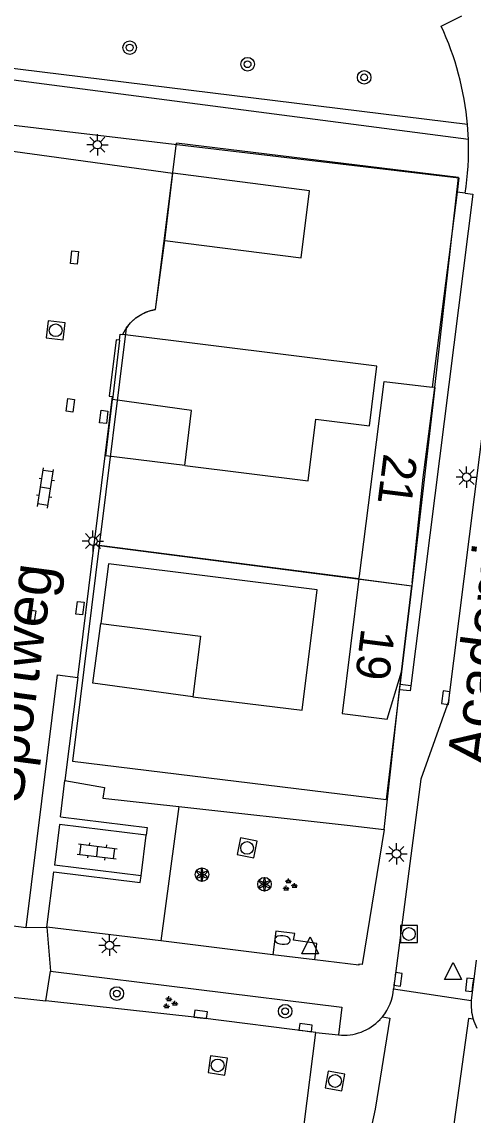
# Model space of a CAD drawing. Extents: x 131000 to 133014, y 396499 to 399001.
# Drawn here: x 132103.1 to 132129.7, y 397102.9 to 397167.2 of the extents above; entities that cross this region are included whole.
import ezdxf

# ---------------------------------------------------------------- set-up
doc = ezdxf.new("R2010")
doc.units = 0
for name, color, linetype in [('gg-afsc-erfafscheiding', 7, 'Continuous'), ('gg-afsc-hekwerk', 7, 'Continuous'), ('gg-anno-openbare ruimte label', 7, 'Continuous'), ('gg-bbg-bijgebouw', 7, 'Continuous'), ('gg-bbg-hoofdgebouw', 7, 'Continuous'), ('gg-bbg-luifel en loopbrug', 7, 'Continuous'), ('gg-bbg-overig bouwwerk', 7, 'Continuous'), ('gg-bbg-tussenscheiding', 7, 'Continuous'), ('gg-knt-verharding', 7, 'Continuous'), ('gg-knt-verharding nz', 7, 'Continuous'), ('gt-afsc-standplaatsafbakening', 7, 'Continuous'), ('gt-anno-standplaatsnummer', 7, 'Continuous'), ('gt-grn-groengrens', 7, 'Continuous'), ('gt-grn-weggrens', 7, 'Continuous'), ('gt-symb-boom', 7, 'Continuous'), ('gt-symb-brandkraan', 7, 'Continuous'), ('gt-symb-groenvak', 7, 'Continuous'), ('gt-symb-klinker verharding', 7, 'Continuous'), ('gt-symb-kolk', 7, 'Continuous'), ('gt-symb-kolk center center', 7, 'Continuous'), ('gt-symb-lichtmast', 7, 'Continuous'), ('gt-symb-rioolschacht', 7, 'Continuous'), ('gt-symb-solitaire heester', 7, 'Continuous'), ('gt-symb-waterafsluiter', 7, 'Continuous')]:
    doc.layers.add(name, color=color, linetype=linetype)

# ---------------------------------------------------------------- blocks, each defined once
blk = doc.blocks.new('gt0-KOLK')
at = {"layer": 'gt-symb-kolk'}
blk.add_lwpolyline([(0, 0), (0.375, 0), (0.375, 0.4), (-0.375, 0.4), (-0.375, 0), (0, 0)], dxfattribs=at)
blk = doc.blocks.new('gt0-LMAST')
at = {"layer": 'gt-symb-lichtmast'}
for p, q in [((-0.182, 0.173), (-0.447, 0.438)), ((-0.005, 0.246), (-0.005, 0.621)), ((0.172, 0.173), (0.437, 0.438)), ((-0.255, -0.004), (-0.63, -0.004)), ((-0.182, -0.181), (-0.447, -0.446)), ((-0.005, -0.254), (-0.005, -0.629)), ((0.437, -0.446), (0.172, -0.181)), ((0.245, -0.004), (0.62, -0.004))]:
    blk.add_line(p, q, dxfattribs=at)
blk.add_circle((-0.005, -0.004), 0.25, dxfattribs=at)
blk = doc.blocks.new('gt0-RS')
at = {"layer": 'gt-symb-rioolschacht'}
blk.add_lwpolyline([(-0.5, -0.5), (0.5, -0.5), (0.5, 0.5), (-0.5, 0.5)], close=True, dxfattribs=at)
blk.add_circle((0, 0), 0.375, dxfattribs=at)
blk = doc.blocks.new('gt0-KOLKCC')
at = {"layer": 'gt-symb-kolk center center'}
blk.add_lwpolyline([(-0.375, 0.2), (0.375, 0.2), (0.375, -0.2), (-0.375, -0.2)], close=True, dxfattribs=at)
blk = doc.blocks.new('gt0-BOOM')
at = {"layer": 'gt-symb-boom'}
for radius in [0.4, 0.2]:
    blk.add_circle((0, 0), radius, dxfattribs=at)
blk = doc.blocks.new('gt0-WAFSL')
at = {"layer": 'gt-symb-waterafsluiter'}
for p, q in [((-0.5, -0.333), (0, 0.667)), ((0, 0.667), (0.5, -0.333)), ((0.5, -0.333), (-0.5, -0.333))]:
    blk.add_line(p, q, dxfattribs=at)
blk = doc.blocks.new('gt0-SH')
at = {"layer": 'gt-symb-solitaire heester'}
blk.add_circle((0, 0), 0.4, dxfattribs=at)
for centre, start, end in [((-0.346, 0.2), 270, 30), ((-0.346, -0.2), 330, 90), ((0, 0.4), 210, 330), ((0.346, 0.2), 150, 270), ((0.346, -0.2), 90, 210), ((0, -0.4), 30, 150)]:
    blk.add_arc(centre, 0.4, start, end, dxfattribs=at)
blk = doc.blocks.new('gt0-BR')
at = {"layer": 'gt-symb-brandkraan'}
for centre, radius, start, end in [((-0.244, 0), 0.206, 107.56694, 252.43307), ((0.599, -2.664), 3, 106.89205, 107.56694), ((0, -0.691), 0.938, 73.10799, 106.89205), ((-0.599, -2.664), 3, 72.43309, 73.10799), ((0.244, 0), 0.206, 287.56695, 72.43309), ((0.599, 2.664), 3, 252.43307, 253.10797), ((0, 0.691), 0.938, 253.10797, 286.89206), ((-0.599, 2.664), 3, 286.89206, 287.56695)]:
    blk.add_arc(centre, radius, start, end, dxfattribs=at)
blk = doc.blocks.new('gt0-GRVAK')
at = {"layer": 'gt-symb-groenvak'}
for p, q in [((-0.11, 0.189), (-0.228, 0.24)), ((-0.182, 0.153), (0.088, 0.153)), ((-0.091, 0.211), (-0.156, 0.322)), ((-0.047, 0.214), (-0.047, 0.393)), ((-0.004, 0.211), (0.061, 0.322)), ((0.015, 0.189), (0.133, 0.24)), ((0.262, -0.052), (0.197, 0.059)), ((0.305, -0.049), (0.305, 0.13)), ((0.349, -0.052), (0.414, 0.059)), ((-0.245, -0.228), (-0.363, -0.177)), ((-0.318, -0.264), (-0.047, -0.264)), ((-0.226, -0.206), (-0.291, -0.095)), ((-0.183, -0.203), (-0.183, -0.024)), ((-0.139, -0.206), (-0.074, -0.095)), ((-0.12, -0.228), (-0.002, -0.177)), ((0.243, -0.074), (0.125, -0.023)), ((0.17, -0.11), (0.441, -0.11)), ((0.368, -0.074), (0.486, -0.023))]:
    blk.add_line(p, q, dxfattribs=at)
blk = doc.blocks.new('gt0-KL1')
at = {"layer": 'gt-symb-klinker verharding'}
for p, q in [((-1.15, 0.3), (1.15, 0.3)), ((-1, -0.3), (-1, 0.3)), ((-0.5, 0.3), (-0.5, 0.45)), ((0, -0.3), (0, 0.3)), ((0.5, 0.3), (0.5, 0.45)), ((1, -0.3), (1, 0.3)), ((-1.15, -0.3), (1.15, -0.3)), ((-0.5, -0.45), (-0.5, -0.3)), ((0.5, -0.45), (0.5, -0.3))]:
    blk.add_line(p, q, dxfattribs=at)

msp = doc.modelspace()

# ---------------------------------------------------------------- linework, layer by layer
at = {"layer": 'gg-afsc-erfafscheiding'}
for p, q in [((132122.997, 397134.471), (132107.394, 397136.475)), ((132125.427, 397128.248), (132125.51, 397129)), ((132125.393, 397127.939), (132125.427, 397128.248)), ((132124.486, 397119.73), (132125.393, 397127.939)), ((132112.389, 397121.066), (132111.318, 397113.169)), ((132112.389, 397121.066), (132122.303, 397119.971)), ((132122.303, 397119.971), (132124.486, 397119.73)), ((132111.318, 397113.169), (132104.608, 397113.966))]:
    msp.add_line(p, q, dxfattribs=at)
msp.add_lwpolyline([(132105.676, 397122.601), (132108.006, 397122.197), (132107.911, 397121.561), (132112.389, 397121.066)], dxfattribs=at)
at = {"layer": 'gg-afsc-hekwerk'}
msp.add_line((132128.774, 397157.231), (132127.301, 397145.749), dxfattribs=at)
msp.add_lwpolyline([(132102.15, 397161.233), (132128.882, 397158.069), (132128.774, 397157.231)], dxfattribs=at)
at = {"layer": 'gg-bbg-bijgebouw'}
for p, q in [((132111.55, 397154.39), (132112.03, 397158.35)), ((132122.997, 397134.471), (132123.02, 397134.65)), ((132126.14, 397134.24), (132126.119, 397134.067))]:
    msp.add_line(p, q, dxfattribs=at)
msp.add_lwpolyline([(132111.55, 397154.39), (132119.6, 397153.36), (132120.09, 397157.3), (132112.03, 397158.35)], dxfattribs=at)
at = {"layer": 'gg-bbg-hoofdgebouw'}
msp.add_line((132125.51, 397129), (132126.119, 397134.067), dxfattribs=at)
for points in [[(132123.02, 397134.65), (132123.82, 397140.8), (132124.49, 397146.09), (132127.301, 397145.749)], [(132126.14, 397134.24), (132126.78, 397140.43), (132127.46, 397145.73), (132127.301, 397145.749)], [(132122.997, 397134.471), (132122, 397126.55), (132124.66, 397126.21), (132125.51, 397129)]]:
    msp.add_lwpolyline(points, dxfattribs=at)
at = {"layer": 'gg-bbg-luifel en loopbrug'}
for points in [[(132112.734, 397141.138), (132108.088, 397141.711), (132108.472, 397145.034)], [(132112.734, 397141.138), (132113.139, 397144.383), (132108.472, 397145.034)], [(132113.215, 397127.535), (132107.325, 397128.332), (132107.794, 397131.836)], [(132107.794, 397131.836), (132113.659, 397131.108), (132113.215, 397127.535)]]:
    msp.add_lwpolyline(points, dxfattribs=at)
at = {"layer": 'gg-bbg-overig bouwwerk'}
msp.add_line((132108.882, 397148.516), (132108.472, 397145.034), dxfattribs=at)
for points in [[(132108.882, 397148.516), (132108.924, 397148.87), (132109.063, 397148.853)], [(132112.734, 397141.138), (132120.008, 397140.231), (132120.462, 397143.873), (132123.608, 397143.48), (132124.045, 397146.983), (132109.063, 397148.853)], [(132113.215, 397127.535), (132119.655, 397126.736), (132120.536, 397133.831), (132108.231, 397135.359), (132107.794, 397131.836)]]:
    msp.add_lwpolyline(points, dxfattribs=at)
at = {"layer": 'gg-bbg-tussenscheiding'}
msp.add_line((132122.997, 397134.471), (132126.119, 397134.067), dxfattribs=at)
at = {"layer": 'gg-knt-verharding'}
for p, q in [((132127.842, 397166.998), (132129.061, 397167.598)), ((132129.441, 397160.331), (132129.387, 397161.216)), ((132111.01, 397150.32), (132111.55, 397154.39)), ((132107.394, 397136.475), (132108.474, 397145.202)), ((132106.428, 397128.674), (132107.394, 397136.475)), ((132106.428, 397128.674), (132105.676, 397122.601)), ((132126.045, 397128.18), (132126.008, 397127.887)), ((132126.008, 397127.887), (132125.393, 397127.939)), ((132105.413, 397120.476), (132105.676, 397122.601)), ((132105.355, 397120.01), (132105.06, 397117.618)), ((132110.457, 397119.379), (132105.355, 397120.01)), ((132110.161, 397116.987), (132110.457, 397119.379)), ((132104.608, 397113.966), (132105.012, 397117.231)), ((132110.161, 397116.987), (132105.06, 397117.618)), ((132099.451, 397114.443), (132103.399, 397113.962)), ((132117.929, 397112.352), (132111.318, 397113.169)), ((132120.399, 397112.047), (132117.929, 397112.352)), ((132122.984, 397111.728), (132120.399, 397112.047)), ((132129.896, 397112.028), (132129.611, 397109.658)), ((132104.552, 397109.642), (132104.82, 397111.385)), ((132097.105, 397110.46), (132104.552, 397109.642)), ((132124.377, 397108.702), (132124.236, 397108.543)), ((132119.762, 397102.361), (132120.465, 397107.78)), ((132120.465, 397107.78), (132121.792, 397107.632))]:
    msp.add_line(p, q, dxfattribs=at)
for points in [[(132101.64, 397155.169), (132102.18, 397159.69), (132112.03, 397158.35)], [(132128.291, 397127.305), (132131.934, 397156.109), (132132.186, 397158.321)], [(132129.263, 397157.173), (132129.707, 397157.106), (132126.045, 397128.18)], [(132103.399, 397113.962), (132105.237, 397128.821), (132106.428, 397128.674)], [(132128.291, 397127.305), (132126.648, 397122.688), (132125.03, 397110.339)], [(132105.413, 397120.476), (132110.515, 397119.845), (132110.457, 397119.379)], [(132124.486, 397119.73), (132123.194, 397111.781), (132122.994, 397111.803), (132122.984, 397111.728)], [(132105.012, 397117.231), (132110.113, 397116.6), (132110.161, 397116.987)], [(132120.399, 397112.047), (132120.508, 397113.022), (132119.143, 397113.203), (132119.212, 397113.608), (132118.1, 397113.743), (132117.929, 397112.352)], [(132104.82, 397111.385), (132121.989, 397109.256), (132121.792, 397107.632)], [(132120.465, 397107.78), (132113.647, 397108.64), (132104.552, 397109.642)], [(132124.377, 397108.702), (132124.814, 397108.623), (132123.947, 397103.255), (132123.172, 397099.648), (132122.982, 397099.69)], [(132129.725, 397108.569), (132129.455, 397108.594), (132128.224, 397099.836), (132128.511, 397099.801)]]:
    msp.add_lwpolyline(points, dxfattribs=at)
for centre, radius, start, end in [((132111.699, 397159.604), 20.528, 356.41592, 63.83304), ((132112.183, 397159.716), 17.269, 4.98192, 24.93888), ((132112.114, 397159.724), 17.338, 351.54038, 2.00752), ((132111.451, 397147.71), 2.647, 99.58143, 154.4122), ((132122.119, 397110.551), 2.919, 320.67986, 355.82598), ((132132.666, 397109.427), 3.064, 175.68364, 196.26864), ((132122.091, 397110.564), 2.948, 264.18357, 316.70227), ((132132.663, 397109.424), 3.06, 196.22211, 206.97239)]:
    msp.add_arc(centre, radius, start, end, dxfattribs=at)
at = {"layer": 'gg-knt-verharding nz'}
msp.add_lwpolyline([(132108.882, 397148.516), (132108.701, 397148.539), (132108.276, 397145.228), (132108.474, 397145.202)], dxfattribs=at)
at = {"layer": 'gt-afsc-standplaatsafbakening'}
for p, q in [((132111.01, 397150.32), (132112.244, 397160.115)), ((132128.859, 397158.099), (132112.244, 397160.115)), ((132127.46, 397145.73), (132128.859, 397158.099)), ((132109.273, 397149.216), (132107.691, 397136.437)), ((132127.46, 397145.73), (132126.119, 397134.067)), ((132107.691, 397136.437), (132106.12, 397123.75)), ((132107.691, 397136.437), (132126.119, 397134.067)), ((132126.119, 397134.067), (132125.51, 397129)), ((132125.51, 397129), (132124.605, 397121.478)), ((132106.12, 397123.75), (132124.605, 397121.478))]:
    msp.add_line(p, q, dxfattribs=at)
msp.add_lwpolyline([(132109.273, 397149.216), (132109.54, 397149.544), (132109.855, 397149.825), (132110.212, 397150.051), (132110.6, 397150.218), (132111.01, 397150.32)], dxfattribs=at)
at = {"layer": 'gt-grn-groengrens'}
for p, q in [((132129.263, 397157.173), (132128.774, 397157.231)), ((132126.045, 397128.18), (132125.427, 397128.248))]:
    msp.add_line(p, q, dxfattribs=at)
for points in [[(132129.387, 397161.216), (132092.816, 397165.695), (132087.365, 397170.601)], [(132129.441, 397160.331), (132091.634, 397165.243), (132091.38, 397162.508)]]:
    msp.add_lwpolyline(points, dxfattribs=at)
at = {"layer": 'gt-grn-weggrens'}
for p, q in [((132103.399, 397113.962), (132104.608, 397113.966)), ((132104.608, 397113.966), (132104.82, 397111.385)), ((132125.03, 397110.339), (132129.611, 397109.658))]:
    msp.add_line(p, q, dxfattribs=at)

# ---------------------------------------------------------------- block references
at = {"layer": 'gt-symb-boom'}
for p in [(132109.488, 397165.732), (132116.435, 397164.757), (132123.302, 397163.984), (132108.729, 397110.065), (132118.648, 397109.026)]:
    msp.add_blockref('gt0-BOOM', p, dxfattribs=at)
at = {"layer": 'gt-symb-brandkraan', "rotation": -4.701808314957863}
msp.add_blockref('gt0-BR', (132118.492, 397113.219), dxfattribs=at)
at = {"layer": 'gt-symb-groenvak'}
for p in [(132118.896, 397116.442), (132111.85, 397109.511)]:
    msp.add_blockref('gt0-GRVAK', p, dxfattribs=at)
at = {"layer": 'gt-symb-klinker verharding'}
for p, rotation in [((132104.53, 397139.82), 80.97080115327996), ((132107.582, 397118.434), -7.068140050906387)]:
    msp.add_blockref('gt0-KL1', p, dxfattribs=dict(at, rotation=rotation))
at = {"layer": 'gt-symb-kolk'}
for p, rotation in [((132128.31, 397127.454), 82.81812146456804), ((132125.102, 397110.932), -97.6405042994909), ((132129.711, 397110.558), 82.81812146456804), ((132113.647, 397108.64), -7.181878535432), ((132119.823, 397107.865), -7.530253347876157)]:
    msp.add_blockref('gt0-KOLK', p, dxfattribs=dict(at, rotation=rotation))
at = {"layer": 'gt-symb-kolk center center'}
for p, rotation in [((132106.241, 397153.38), 83.7420660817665), ((132105.987, 397144.685), 82.87498365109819), ((132107.962, 397144.001), 82.8749836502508), ((132103.698, 397132.251), 81.48906580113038), ((132106.56, 397132.747), 82.99574075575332)]:
    msp.add_blockref('gt0-KOLKCC', p, dxfattribs=dict(at, rotation=rotation))
at = {"layer": 'gt-symb-lichtmast', "rotation": 90}
for p in [(132107.582, 397160.024), (132107.318, 397136.695)]:
    msp.add_blockref('gt0-LMAST', p, dxfattribs=at)
at = {"layer": 'gt-symb-lichtmast'}
for p in [(132129.344, 397140.463), (132125.213, 397118.291), (132108.302, 397112.908)]:
    msp.add_blockref('gt0-LMAST', p, dxfattribs=at)
at = {"layer": 'gt-symb-rioolschacht'}
for p, rotation in [((132105.128, 397149.1), -7.0042592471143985), ((132116.403, 397118.638), 78.52151796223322), ((132114.673, 397105.84), 81.2538377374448), ((132121.586, 397104.919), 80.27403432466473)]:
    msp.add_blockref('gt0-RS', p, dxfattribs=dict(at, rotation=rotation))
msp.add_blockref('gt0-RS', (132125.94, 397113.573), dxfattribs=at)
at = {"layer": 'gt-symb-solitaire heester'}
for p in [(132113.746, 397117.067), (132117.43, 397116.5)]:
    msp.add_blockref('gt0-SH', p, dxfattribs=at)
at = {"layer": 'gt-symb-waterafsluiter'}
for p in [(132120.122, 397112.735), (132128.544, 397111.234)]:
    msp.add_blockref('gt0-WAFSL', p, dxfattribs=at)

# ---------------------------------------------------------------- texts
at = {"layer": 'gg-anno-openbare ruimte label'}
for s, rotation, p in [('Academiepad', 82.8, (132130.66, 397123.389)), ('Sportweg', 82.5, (132103.154, 397121.194))]:
    msp.add_text(s, height=2.5, rotation=rotation, dxfattribs=at).set_placement(p)
at = {"layer": 'gt-anno-standplaatsnummer'}
for s, rotation, p in [('21', 262.82528, (132124.462, 397141.894)), ('19', 262.81812, (132123.141, 397131.604))]:
    msp.add_text(s, height=2, rotation=rotation, dxfattribs=at).set_placement(p)

doc.saveas('drawing.dxf')
